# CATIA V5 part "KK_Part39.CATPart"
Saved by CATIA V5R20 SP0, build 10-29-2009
Part number: Galet2
Bounding box of the stored display mesh (mm): x 9 to 13.5, y 180.003 to 199.997, z 5.003 to 24.997
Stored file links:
  G:\Khaled_CFAO_2011\ST2M\ST2M_GR2\aandujar\Khaled\CAD_thinkMOTION\KK_Part39.CATPart
  G:\Khaled_CFAO_2011\ST2M\ST2M_GR2\aandujar\Khaled\CAD_thinkMOTION\KK_Aandujar.CATProduct
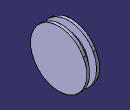
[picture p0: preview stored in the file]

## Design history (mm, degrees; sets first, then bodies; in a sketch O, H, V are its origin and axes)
WSupportSet1: ActiveGrid {3dwsupport RefPoint {point stored without definition}, 3DWOS ({wsupport Support xy-plane, RefPoint {3dwsupport}, GridIn {cartgrid Value 100, Stepbid1 0, Value 100, Stepbid2 0, Direction (1, 0, 0)}, GeometricData ({line type PtDir, Direction (1, 0, 0), Support xy-plane}; {line type PtDir, Direction (0, 1, 0), Support yz-plane})}; {wsupport Support yz-plane, RefPoint {3dwsupport}, GridIn {cartgrid Value 100, Stepbid1 0, Value 100, Stepbid2 0, Direction (0, 1, 0)}, GeometricData ({line type PtDir, Direction (0, 1, 0), Support yz-plane}; {line type PtDir, Direction (0, 0, 1), Support zx-plane})}; {wsupport Support zx-plane, RefPoint {3dwsupport}, GridIn {cartgrid Value 100, Stepbid1 0, Value 100, Stepbid2 0, Direction (0, 0, 1)}, GeometricData ({line type PtDir, Direction (0, 0, 1), Support zx-plane}; {line type PtDir, Direction (1, 0, 0), Support xy-plane})}), GeometricData ({line type PtDir, RefPoint {point stored without definition}, Direction (1, 0, 0), Support xy-plane}; {line type PtDir, RefPoint {point stored without definition}, Direction (0, 1, 0), Support yz-plane}; {line type PtDir, RefPoint {point stored without definition}, Direction (0, 0, 1), Support zx-plane})}
Set1
  Plane1: stored without definition
  Sketch1 on Plane1, origin (0, 0, 15), H (1, 0, 0), V (0, 1, 0)
    line L1 (9, 190) -> (13.5, 190)
    line L2 (13.5, 190) -> (13.5, 180)
    line L3 (13.5, 180) -> (12.5, 180)
    line L4 (12.5, 180) -> (12.5, 183)
    line L5 (12.5, 183) -> (10, 183)
    line L6 (10, 183) -> (10, 180)
    point P7 (10, 180)
    line L7 (10, 180) -> (9, 180)
    line L8 (9, 180) -> (9, 190)
    reference intersected line E1 through (12.5, 0) direction (0, 1) from Plane2
    reference projected line E2 (-7.5, 190) -> (32.5, 190) from Line1
    length L3 = 1
    length L7 = 1
    distance L4 L6 = 2.5
    distance L5 L1 = 7
    distance L1 L3 = 10
    horizontal: L1 H, L3 H, L5 H, L7 H
    vertical: L2 V, L4 V, L6 V, L8 V
    coincidence: P7 L3, L4 E1, L1 E2
Set2
  Plane2 "Plan.Ref5": linked copy from another document
  Line1 "Axe_pivot_galet2": linked copy from another document
Body1 (main body)
  Shaft1: profile Sketch1, axis Line1, angle 360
